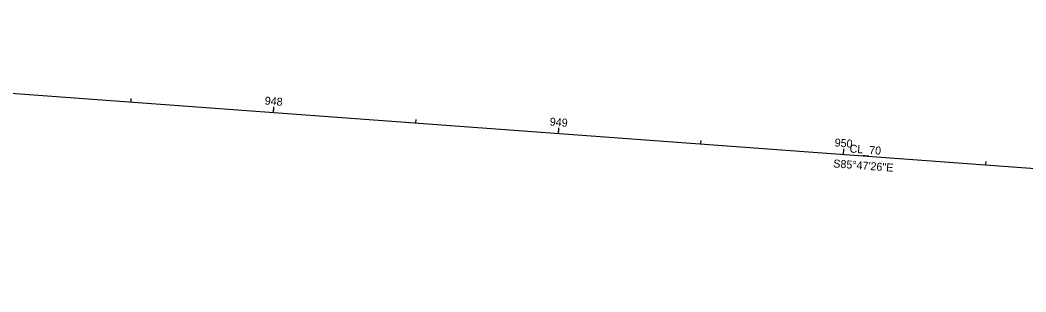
# Model space of a CAD drawing. Extents: x 1981066 to 1984208, y 708139 to 709503.
# Drawn here: x 1981417.5 to 1981769.5, y 708968.6 to 709063.9 of the extents above; entities that cross this region are included whole.
import ezdxf

# ---------------------------------------------------------------- set-up
doc = ezdxf.new("R2010")
doc.units = 0
for name, color, linetype in [('DT_X_Break_Line', 7, 'Continuous'), ('GE_X_Cells', 7, 'Continuous'), ('PM_X_Dotted_Line', 7, 'Continuous'), ('PM_X_Edge_Line', 7, 'Continuous'), ('PV_P_EOP', 7, 'Continuous'), ('RD_X_Wall', 7, 'Continuous'), ('SV_X_Break_Lines', 7, 'Continuous'), ('SV_X_Text_Elevation', 7, 'Continuous'), ('SV_X_Text_Name', 7, 'Continuous'), ('TopoDOT_Transients', 7, 'Continuous')]:
    doc.layers.add(name, color=color, linetype=linetype)

msp = doc.modelspace()

# ---------------------------------------------------------------- linework, layer by layer
at = {"layer": 'PM_X_Edge_Line'}
for p, q in [((1981456.32, 709035.15), (1981456.4, 709036.34)), ((1981506.18, 709031.48), (1981506.33, 709033.47)), ((1981556.05, 709027.81), (1981556.13, 709029)), ((1981605.91, 709024.14), (1981606.06, 709026.13)), ((1981655.78, 709020.47), (1981655.86, 709021.66)), ((1981705.64, 709016.8), (1981705.79, 709018.79)), ((1981755.51, 709013.12), (1981755.59, 709014.32))]:
    msp.add_line(p, q, dxfattribs=at)
at = {"layer": 'PV_P_EOP'}
msp.add_line((1981705.64, 709016.8), (1981705.79, 709018.79), dxfattribs=at)
at = {"layer": 'RD_X_Wall'}
for p, q in [((1981506.18, 709031.48), (1981506.27, 709032.67)), ((1981605.91, 709024.14), (1981606, 709025.33)), ((1981705.64, 709016.8), (1981705.79, 709018.79))]:
    msp.add_line(p, q, dxfattribs=at)
at = {"layer": 'SV_X_Break_Lines'}
msp.add_line((1981066.12, 709063.86), (1982360.68, 708968.58), dxfattribs=at)
msp.add_line((1981066.12, 709063.86), (1982360.68, 708968.58), dxfattribs=at)

# ---------------------------------------------------------------- texts
at = {"layer": 'DT_X_Break_Line'}
msp.add_text('CL_70', height=2.8, rotation=355.7906, dxfattribs=at).set_placement((1981707.7, 709017.47))
at = {"layer": 'GE_X_Cells'}
msp.add_text('S85°47\'26"E', height=2.8, rotation=355.7906, dxfattribs=at).set_placement((1981702.01, 709012.25))
at = {"layer": 'PM_X_Dotted_Line'}
msp.add_text('S85°47\'26"E', height=2.8, rotation=355.7906, dxfattribs=at).set_placement((1981702.01, 709012.25))
at = {"layer": 'PM_X_Edge_Line'}
for s, p in [('948', (1981503.04, 709034.26)), ('949', (1981602.79, 709026.91)), ('950', (1981702.49, 709019.58))]:
    msp.add_text(s, height=2.8, rotation=355.7906, dxfattribs=at).set_placement(p)
at = {"layer": 'PV_P_EOP'}
msp.add_text('950', height=2.8, rotation=355.7906, dxfattribs=at).set_placement((1981702.49, 709019.58))
at = {"layer": 'RD_X_Wall'}
msp.add_text('950', height=2.8, rotation=355.7906, dxfattribs=at).set_placement((1981702.49, 709019.58))
at = {"layer": 'SV_X_Text_Elevation'}
msp.add_text('CL_70', height=2.8, rotation=355.7906, dxfattribs=at).set_placement((1981707.7, 709017.47))
at = {"layer": 'SV_X_Text_Name'}
msp.add_text('CL_70', height=2.8, rotation=355.7906, dxfattribs=at).set_placement((1981707.7, 709017.47))
at = {"layer": 'TopoDOT_Transients'}
msp.add_text('S85°47\'26"E', height=2.8, rotation=355.7906, dxfattribs=at).set_placement((1981702.01, 709012.25))

doc.saveas('drawing.dxf')
